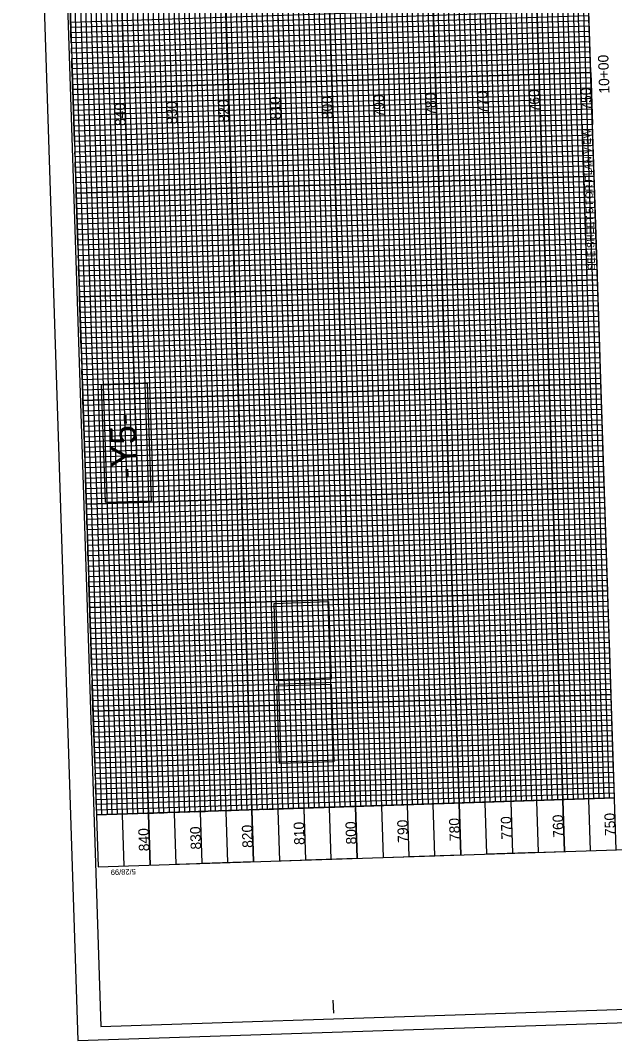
# Model space of a CAD drawing. Extents: x 1627314 to 1628469, y 762309 to 764247.
# Drawn here: x 1627314 to 1627888, y 762309 to 763293 of the extents above; entities that cross this region are included whole.
import ezdxf

# ---------------------------------------------------------------- set-up
doc = ezdxf.new("R2010")
doc.units = 0
for name, color, linetype in [('Exist Vertical Profile Horizontal Axis Label Major', 7, 'Continuous'), ('Exist Vertical Profile Vertical Axis Label', 7, 'Continuous'), ('Prop DSN Text', 7, 'Continuous'), ('Prop Grid Mask', 7, 'Continuous'), ('Sheet Data Field CELL', 7, 'Continuous'), ('Sheet DOT Grid CELL', 7, 'Continuous'), ('Sheet Layout Profile Border Port 1', 7, 'Continuous'), ('Sheet Plot Border Inside CELL', 7, 'Continuous'), ('Sheet Plot Border Outside CELL', 7, 'Continuous'), ('Sheet Profile CELL', 7, 'Continuous'), ('Sheet Profile Grid Major CELL', 7, 'Continuous'), ('Sheet Profile Grid Middle CELL', 7, 'Continuous'), ('Sheet Profile Grid Minor CELL', 7, 'Continuous')]:
    doc.layers.add(name, color=color, linetype=linetype)

msp = doc.modelspace()

# ---------------------------------------------------------------- linework, layer by layer
at = {"layer": 'Prop Grid Mask'}
for points in [[(1627366.44, 763176.67), (1627364.8, 763226.64), (1627864.53, 763242.99), (1627866.17, 763193.01)], [(1627856.17, 763192.69), (1627860.92, 763047.76), (1627870.91, 763048.09), (1627866.17, 763193.01)], [(1627440.71, 762829.99), (1627437.01, 762943.01), (1627392.29, 762941.55), (1627395.99, 762828.53)], [(1627561.47, 762656.22), (1627559.02, 762731.05), (1627611.64, 762732.77), (1627614.09, 762657.94)], [(1627564.08, 762576.52), (1627561.63, 762651.35), (1627614.24, 762653.07), (1627616.69, 762578.24)]]:
    msp.add_lwpolyline(points, close=True, dxfattribs=at)
at = {"layer": 'Sheet DOT Grid CELL'}
for p, q in [((1627590.15, 763984.41), (1627639.19, 762485.21)), ((1627640.12, 763986.05), (1627689.16, 762486.85)), ((1627690.1, 763987.68), (1627739.13, 762488.48)), ((1627740.07, 763989.32), (1627789.11, 762490.12)), ((1627790.04, 763990.95), (1627839.08, 762491.75)), ((1627396.8, 763777.93), (1627439.29, 762478.68)), ((1627446.77, 763779.57), (1627489.27, 762480.31)), ((1627496.74, 763781.25), (1627539.24, 762481.95)), ((1627546.72, 763782.83), (1627589.21, 762483.58)), ((1627862.9, 763292.96), (1627363.17, 763276.61)), ((1627864.53, 763242.99), (1627364.8, 763226.64)), ((1627866.17, 763193.01), (1627366.44, 763176.67)), ((1627867.8, 763143.04), (1627368.07, 763126.69)), ((1627869.44, 763093.07), (1627369.71, 763076.72)), ((1627871.07, 763043.09), (1627371.34, 763026.75)), ((1627872.71, 762993.12), (1627372.98, 762976.77)), ((1627874.34, 762943.15), (1627374.61, 762926.8)), ((1627875.98, 762893.17), (1627376.24, 762876.83)), ((1627877.61, 762843.2), (1627377.88, 762826.85)), ((1627879.25, 762793.23), (1627379.51, 762776.88)), ((1627880.88, 762743.25), (1627381.15, 762726.91)), ((1627882.52, 762693.28), (1627382.78, 762676.93)), ((1627884.15, 762643.31), (1627384.42, 762626.96)), ((1627885.78, 762593.33), (1627386.05, 762576.99)), ((1627887.42, 762543.36), (1627387.69, 762527.01))]:
    msp.add_line(p, q, dxfattribs=at)
at = {"layer": 'Sheet Layout Profile Border Port 1'}
msp.add_lwpolyline([(1627548.65, 762532.28), (1627887.42, 762543.36), (1627841.65, 763942.61), (1627566.8, 763933.62)], dxfattribs=at)
at = {"layer": 'Sheet Plot Border Inside CELL'}
msp.add_lwpolyline([(1628446.34, 762357.53), (1628391.86, 764023.14), (1627337.33, 763988.65), (1627391.81, 762323.04)], close=True, dxfattribs=at)
at = {"layer": 'Sheet Plot Border Outside CELL'}
msp.add_lwpolyline([(1628469.21, 762345.27), (1628413.63, 764044.37), (1627314.22, 764008.4), (1627369.79, 762309.31)], close=True, dxfattribs=at)
at = {"layer": 'Sheet Profile CELL'}
for p, q in [((1627889.05, 762493.39), (1627840.02, 763992.59)), ((1627616.56, 762335.89), (1627616.15, 762348.39))]:
    msp.add_line(p, q, dxfattribs=at)
msp.add_lwpolyline([(1627340.28, 763976.24), (1627389.32, 762477.04), (1628438.76, 762511.37), (1628389.72, 764010.57)], close=True, dxfattribs=at)
at = {"layer": 'Sheet Profile Grid Major CELL'}
for points in [[(1627546.71, 763782.88), (1627589.21, 762483.58), (1627639.19, 762485.21), (1627590.15, 763984.41)], [(1627640.12, 763986.05), (1627689.16, 762486.85), (1627739.13, 762488.48), (1627690.1, 763987.68)], [(1627740.07, 763989.32), (1627789.11, 762490.12), (1627789.11, 762490.12), (1627839.08, 762491.75), (1627790.04, 763990.95)], [(1627439.29, 762478.68), (1627396.79, 763777.98)], [(1627446.77, 763779.62), (1627489.27, 762480.31), (1627539.24, 762481.95), (1627496.74, 763781.25)], [(1627387.69, 762527.01), (1627887.42, 762543.36), (1627885.78, 762593.33), (1627386.05, 762576.99), (1627384.42, 762626.96), (1627884.15, 762643.31), (1627882.52, 762693.28), (1627382.78, 762676.93), (1627381.15, 762726.91), (1627880.88, 762743.25), (1627879.25, 762793.23), (1627379.51, 762776.88), (1627377.88, 762826.85), (1627877.61, 762843.2), (1627875.98, 762893.17), (1627376.24, 762876.83), (1627374.61, 762926.8), (1627874.34, 762943.15), (1627872.71, 762993.12), (1627372.98, 762976.77), (1627371.34, 763026.75), (1627871.07, 763043.09), (1627869.44, 763093.07), (1627369.71, 763076.72), (1627368.07, 763126.69), (1627867.8, 763143.04), (1627866.17, 763193.01), (1627366.44, 763176.67), (1627364.8, 763226.64), (1627864.53, 763242.99), (1627862.9, 763292.96), (1627363.17, 763276.61), (1627361.53, 763326.59)]]:
    msp.add_lwpolyline(points, dxfattribs=at)
at = {"layer": 'Sheet Profile Grid Middle CELL'}
msp.add_line((1627414.31, 762477.86), (1627371.81, 763777.11), dxfattribs=at)
for points in [[(1627815.03, 763991.77), (1627864.07, 762492.57)], [(1627615.14, 763985.23), (1627664.17, 762486.03), (1627714.15, 762487.67), (1627665.11, 763986.86)], [(1627715.08, 763988.5), (1627764.12, 762489.3), (1627814.09, 762490.94), (1627765.06, 763990.13)], [(1627521.73, 763782.02), (1627564.23, 762482.76), (1627614.2, 762484.4), (1627570.88, 763808.69)], [(1627421.78, 763778.8), (1627464.28, 762479.49), (1627514.25, 762481.13), (1627471.75, 763780.43)], [(1627386.87, 762552), (1627886.6, 762568.35), (1627884.97, 762618.32), (1627385.23, 762601.97), (1627383.6, 762651.95), (1627883.33, 762668.29), (1627881.7, 762718.27), (1627381.97, 762701.92), (1627380.33, 762751.89), (1627880.06, 762768.24), (1627878.43, 762818.21), (1627378.7, 762801.87), (1627377.06, 762851.84), (1627876.79, 762868.19), (1627875.16, 762918.16), (1627375.43, 762901.81), (1627373.79, 762951.79), (1627873.53, 762968.13), (1627871.89, 763018.11), (1627372.16, 763001.76), (1627370.52, 763051.73), (1627870.26, 763068.08), (1627868.62, 763118.05), (1627868.62, 763118.05), (1627368.89, 763101.71), (1627367.25, 763151.68), (1627866.99, 763168.03), (1627865.35, 763218), (1627365.62, 763201.65), (1627363.98, 763251.63), (1627863.72, 763267.97), (1627862.08, 763317.95)]]:
    msp.add_lwpolyline(points, dxfattribs=at)
at = {"layer": 'Sheet Profile Grid Minor CELL'}
for p, q in [((1627867.43, 762542.71), (1627821.66, 763941.96)), ((1627826.66, 763942.12), (1627872.43, 762542.87)), ((1627877.42, 762543.03), (1627831.66, 763942.29)), ((1627576.79, 763933.95), (1627622.56, 762534.7)), ((1627627.56, 762534.86), (1627581.79, 763934.11)), ((1627586.79, 763934.28), (1627632.56, 762535.02)), ((1627642.55, 762535.35), (1627596.78, 763934.6)), ((1627601.78, 763934.77), (1627647.55, 762535.51)), ((1627652.55, 762535.68), (1627606.78, 763934.93)), ((1627611.77, 763935.09), (1627657.54, 762535.84)), ((1627667.54, 762536.17), (1627621.77, 763935.42)), ((1627626.77, 763935.58), (1627672.53, 762536.33)), ((1627677.53, 762536.5), (1627631.76, 763935.75)), ((1627636.76, 763935.91), (1627682.53, 762536.66)), ((1627692.52, 762536.99), (1627646.75, 763936.24)), ((1627651.75, 763936.4), (1627697.52, 762537.15)), ((1627702.52, 762537.31), (1627656.75, 763936.56)), ((1627661.75, 763936.73), (1627707.52, 762537.48)), ((1627717.51, 762537.8), (1627671.74, 763937.05)), ((1627676.74, 763937.22), (1627722.51, 762537.97)), ((1627727.51, 762538.13), (1627681.74, 763937.38)), ((1627686.73, 763937.55), (1627732.5, 762538.29)), ((1627742.5, 762538.62), (1627696.73, 763937.87)), ((1627701.73, 763938.04), (1627747.49, 762538.78)), ((1627752.49, 762538.95), (1627706.72, 763938.2)), ((1627711.72, 763938.36), (1627757.49, 762539.11)), ((1627767.48, 762539.44), (1627721.71, 763938.69)), ((1627726.71, 763938.85), (1627772.48, 762539.6)), ((1627731.71, 763939.02), (1627777.48, 762539.76)), ((1627736.71, 763939.18), (1627782.48, 762539.93)), ((1627792.47, 762540.25), (1627746.7, 763939.51)), ((1627751.7, 763939.67), (1627797.47, 762540.42)), ((1627802.47, 762540.58), (1627756.7, 763939.83)), ((1627761.69, 763940), (1627807.46, 762540.75)), ((1627817.46, 762541.07), (1627771.69, 763940.32)), ((1627776.69, 763940.49), (1627822.45, 762541.24)), ((1627827.45, 762541.4), (1627781.68, 763940.65)), ((1627786.68, 763940.81), (1627832.45, 762541.56)), ((1627842.44, 762541.89), (1627796.67, 763941.14)), ((1627801.67, 763941.3), (1627847.44, 762542.05)), ((1627852.44, 762542.22), (1627806.67, 763941.47)), ((1627811.67, 763941.63), (1627857.44, 762542.38)), ((1627392.68, 762527.18), (1627351.82, 763776.51)), ((1627356.82, 763776.67), (1627398.03, 762527.35)), ((1627402.68, 762527.5), (1627361.81, 763776.84)), ((1627481.75, 763780.71), (1627522.61, 762531.43)), ((1627486.75, 763780.92), (1627527.61, 762531.59)), ((1627491.74, 763781.09), (1627532.61, 762531.75)), ((1627542.6, 762532.08), (1627501.74, 763781.41)), ((1627506.74, 763781.58), (1627547.6, 762532.25)), ((1627552.6, 762532.41), (1627511.73, 763781.69)), ((1627531.72, 763782.34), (1627572.59, 762533.06)), ((1627577.59, 762533.23), (1627536.72, 763782.51)), ((1627556.71, 763783.16), (1627597.57, 762533.88)), ((1627602.57, 762534.04), (1627561.71, 763783.33)), ((1627397.68, 762527.34), (1627397.68, 762527.34))]:
    msp.add_line(p, q, dxfattribs=at)
for points in [[(1627836.65, 763942.45), (1627882.42, 762543.2)], [(1627566.71, 763783.49), (1627607.57, 762534.21), (1627617.56, 762534.53), (1627571.79, 763933.79)], [(1627366.81, 763777), (1627407.68, 762527.67), (1627417.67, 762528), (1627376.81, 763777.33)], [(1627381.8, 763777.44), (1627422.67, 762528.16), (1627427.67, 762528.32), (1627386.8, 763777.65)], [(1627391.8, 763777.82), (1627432.66, 762528.49), (1627442.66, 762528.81), (1627401.79, 763778.14)], [(1627406.79, 763778.31), (1627447.65, 762528.98), (1627452.65, 762529.14), (1627411.79, 763778.47)], [(1627416.78, 763778.63), (1627457.65, 762529.3), (1627467.64, 762529.63), (1627426.78, 763778.96)], [(1627431.78, 763779.13), (1627472.64, 762529.79), (1627477.64, 762529.96), (1627436.77, 763779.29)], [(1627441.77, 763779.45), (1627482.64, 762530.12), (1627492.63, 762530.45), (1627451.77, 763779.78)], [(1627456.86, 763779.95), (1627497.72, 762530.71), (1627502.62, 762530.87), (1627461.76, 763780.11)], [(1627466.76, 763780.27), (1627507.62, 762530.94), (1627517.62, 762531.26), (1627476.75, 763780.6)], [(1627516.73, 763781.85), (1627557.6, 762532.57), (1627567.59, 762532.9), (1627526.73, 763782.18)], [(1627541.72, 763782.67), (1627582.58, 762533.39), (1627592.58, 762533.72), (1627551.71, 763783)], [(1627862.57, 763302.95), (1627362.84, 763286.61), (1627362.68, 763291.61), (1627862.41, 763307.95)], [(1627370.36, 763056.73), (1627870.09, 763073.08), (1627869.93, 763078.07), (1627370.2, 763061.73), (1627370.03, 763066.73), (1627869.77, 763083.07), (1627869.6, 763088.07), (1627369.87, 763071.72), (1627369.54, 763081.72), (1627869.28, 763098.06), (1627869.11, 763103.06), (1627369.38, 763086.72), (1627369.22, 763091.71), (1627868.95, 763108.06), (1627868.78, 763113.06), (1627369.05, 763096.71), (1627368.73, 763106.7), (1627868.46, 763123.05), (1627868.29, 763128.05), (1627368.56, 763111.7), (1627368.4, 763116.7), (1627868.13, 763133.05), (1627867.97, 763138.04), (1627368.23, 763121.7), (1627367.91, 763131.69), (1627867.64, 763148.04), (1627867.48, 763153.03), (1627367.74, 763136.69), (1627367.58, 763141.69), (1627867.31, 763158.03), (1627867.15, 763163.03), (1627367.42, 763146.68), (1627367.09, 763156.68), (1627866.82, 763173.02), (1627866.66, 763178.02), (1627366.93, 763161.68), (1627366.76, 763166.67), (1627866.5, 763183.02), (1627866.33, 763188.02), (1627366.6, 763171.67), (1627366.27, 763181.66), (1627866.01, 763198.01), (1627866.01, 763198.01), (1627865.84, 763203.01), (1627366.11, 763186.66), (1627365.95, 763191.66), (1627865.68, 763208.01), (1627865.52, 763213), (1627365.78, 763196.66), (1627365.46, 763206.65), (1627865.19, 763223), (1627865.03, 763227.99), (1627365.29, 763211.65), (1627365.13, 763216.65), (1627864.86, 763232.99), (1627864.7, 763237.99), (1627364.97, 763221.64), (1627364.64, 763231.64), (1627864.37, 763247.98), (1627864.21, 763252.98), (1627364.48, 763236.63), (1627364.31, 763241.63), (1627864.04, 763257.98), (1627863.88, 763262.98), (1627364.15, 763246.63), (1627363.82, 763256.62), (1627863.55, 763272.97), (1627863.39, 763277.97), (1627363.66, 763261.62), (1627363.49, 763266.62), (1627863.23, 763282.97), (1627863.06, 763287.96), (1627363.33, 763271.62), (1627363, 763281.61), (1627862.74, 763297.96)], [(1627880.39, 762758.25), (1627880.23, 762763.24), (1627380.49, 762746.9), (1627380.17, 762756.89), (1627879.9, 762773.24), (1627879.74, 762778.24), (1627380, 762761.89), (1627379.84, 762766.89), (1627879.57, 762783.23), (1627879.41, 762788.23), (1627379.68, 762771.88), (1627379.35, 762781.88), (1627879.08, 762798.22), (1627878.92, 762803.22), (1627379.19, 762786.88), (1627379.02, 762791.87), (1627878.76, 762808.22), (1627878.59, 762813.22), (1627378.86, 762796.87), (1627378.53, 762806.86), (1627878.27, 762823.21), (1627878.1, 762828.21), (1627378.37, 762811.86), (1627378.21, 762816.86), (1627877.94, 762833.21), (1627877.78, 762838.2), (1627378.04, 762821.86), (1627377.72, 762831.85), (1627877.45, 762848.2), (1627877.28, 762853.19), (1627377.55, 762836.85), (1627377.39, 762841.85), (1627877.12, 762858.19), (1627876.96, 762863.19), (1627377.23, 762846.84), (1627376.9, 762856.84), (1627876.63, 762873.18), (1627876.47, 762878.18), (1627376.73, 762861.84), (1627376.57, 762866.83), (1627876.3, 762883.18), (1627876.14, 762888.18), (1627376.41, 762871.83), (1627376.08, 762881.82), (1627875.81, 762898.17), (1627875.65, 762903.17), (1627375.92, 762886.82), (1627375.75, 762891.82), (1627875.49, 762908.17), (1627875.32, 762913.16), (1627375.59, 762896.82), (1627375.26, 762906.81), (1627875, 762923.16), (1627874.83, 762928.15), (1627375.1, 762911.81), (1627374.94, 762916.81), (1627874.67, 762933.15), (1627874.51, 762938.15), (1627374.77, 762921.8), (1627374.45, 762931.8), (1627874.18, 762948.14), (1627874.02, 762953.14), (1627374.28, 762936.8), (1627374.12, 762941.79), (1627873.85, 762958.14), (1627873.69, 762963.14), (1627373.96, 762946.79), (1627373.63, 762956.78), (1627873.36, 762973.13), (1627873.2, 762978.13), (1627373.47, 762961.78), (1627373.3, 762966.78), (1627873.03, 762983.13), (1627872.87, 762988.12), (1627373.14, 762971.78), (1627372.81, 762981.77), (1627872.54, 762998.12), (1627872.38, 763003.11), (1627372.65, 762986.77), (1627372.48, 762991.77), (1627872.22, 763008.11), (1627872.05, 763013.11), (1627372.32, 762996.76), (1627371.99, 763006.76), (1627871.73, 763023.1), (1627871.56, 763028.1), (1627371.83, 763011.76), (1627371.67, 763016.75), (1627871.4, 763033.1), (1627871.24, 763038.1), (1627371.5, 763021.75), (1627371.18, 763031.74), (1627870.91, 763048.09), (1627870.75, 763053.09), (1627371.01, 763036.74), (1627370.85, 763041.74), (1627870.58, 763058.09), (1627870.42, 763063.08), (1627370.69, 763046.74), (1627370.36, 763056.73)], [(1627387.52, 762532.01), (1627887.26, 762548.36), (1627887.09, 762553.36), (1627387.36, 762537.01), (1627387.2, 762542.01), (1627886.93, 762558.35), (1627886.77, 762563.35), (1627387.03, 762547), (1627386.71, 762557), (1627886.44, 762573.34), (1627886.28, 762578.34), (1627386.54, 762562), (1627386.38, 762566.99), (1627886.11, 762583.34), (1627885.95, 762588.34), (1627885.62, 762598.33), (1627885.46, 762603.33), (1627385.73, 762586.98), (1627385.56, 762591.98), (1627885.29, 762608.33), (1627885.13, 762613.32), (1627385.4, 762596.98), (1627385.07, 762606.97), (1627884.8, 762623.32), (1627884.64, 762628.32), (1627384.91, 762611.97), (1627384.74, 762616.97), (1627884.48, 762633.31), (1627884.31, 762638.31), (1627384.58, 762621.96), (1627384.25, 762631.96), (1627883.99, 762648.3), (1627883.82, 762653.3), (1627384.09, 762636.96), (1627383.93, 762641.95), (1627883.66, 762658.3), (1627883.5, 762663.3), (1627383.76, 762646.95), (1627383.44, 762656.95), (1627883.17, 762673.29), (1627883.01, 762678.29), (1627383.27, 762661.94), (1627383.11, 762666.94), (1627882.84, 762683.29), (1627882.68, 762688.28), (1627382.95, 762671.94), (1627382.62, 762681.93), (1627882.35, 762698.28), (1627882.19, 762703.28), (1627382.46, 762686.93), (1627382.29, 762691.93), (1627882.03, 762708.27), (1627881.86, 762713.27), (1627382.13, 762696.92), (1627381.8, 762706.92), (1627881.53, 762723.26), (1627881.37, 762728.26), (1627381.64, 762711.92), (1627381.48, 762716.91), (1627881.21, 762733.26), (1627881.04, 762738.26), (1627381.31, 762721.91), (1627380.98, 762731.9), (1627880.72, 762748.25), (1627880.55, 762753.25), (1627380.82, 762736.9), (1627380.66, 762741.9), (1627880.39, 762758.25)], [(1627885.95, 762588.34), (1627386.22, 762571.99), (1627385.89, 762581.99), (1627885.62, 762598.33)]]:
    msp.add_lwpolyline(points, dxfattribs=at)

# ---------------------------------------------------------------- texts
at = {"layer": 'Exist Vertical Profile Horizontal Axis Label Major'}
msp.add_text('10+00', height=10, rotation=91.87347, dxfattribs=at).set_placement((1627882.7, 763222.88))
at = {"layer": 'Exist Vertical Profile Vertical Axis Label'}
for s, p in [('770', (1627765.53, 763203.16)), ('760', (1627815.51, 763204.8)), ('750', (1627865.48, 763206.43)), ('830', (1627465.69, 763193.35)), ('820', (1627515.67, 763194.99)), ('810', (1627565.6, 763197.82)), ('800', (1627615.61, 763198.26)), ('790', (1627665.59, 763199.89)), ('780', (1627715.56, 763201.53)), ('840', (1627415.72, 763191.72)), ('770', (1627788.42, 762503.53)), ('760', (1627838.39, 762505.17)), ('750', (1627888.37, 762506.8)), ('830', (1627488.58, 762493.73)), ('820', (1627538.55, 762495.36)), ('810', (1627588.49, 762498.19)), ('800', (1627638.5, 762498.63)), ('790', (1627688.47, 762500.27)), ('780', (1627738.45, 762501.9)), ('840', (1627438.61, 762492.09))]:
    msp.add_text(s, height=10, rotation=91.87347, dxfattribs=at).set_placement(p)
at = {"layer": 'Prop DSN Text'}
msp.add_text('SEE SHEET 5 FOR PLAN VIEW', height=7, rotation=91.87347, dxfattribs=at).set_placement((1627868.81, 763052.61))
at = {"layer": 'Sheet Data Field CELL'}
msp.add_text('-Y5-', height=25, rotation=91.87347, dxfattribs=at).set_placement((1627426.96, 762851.27))
at = {"layer": 'Sheet Profile CELL'}
msp.add_text('5/28/99', height=5.25, rotation=181.87347, dxfattribs=at).set_placement((1627425.5, 762474.99))

doc.saveas('drawing.dxf')
